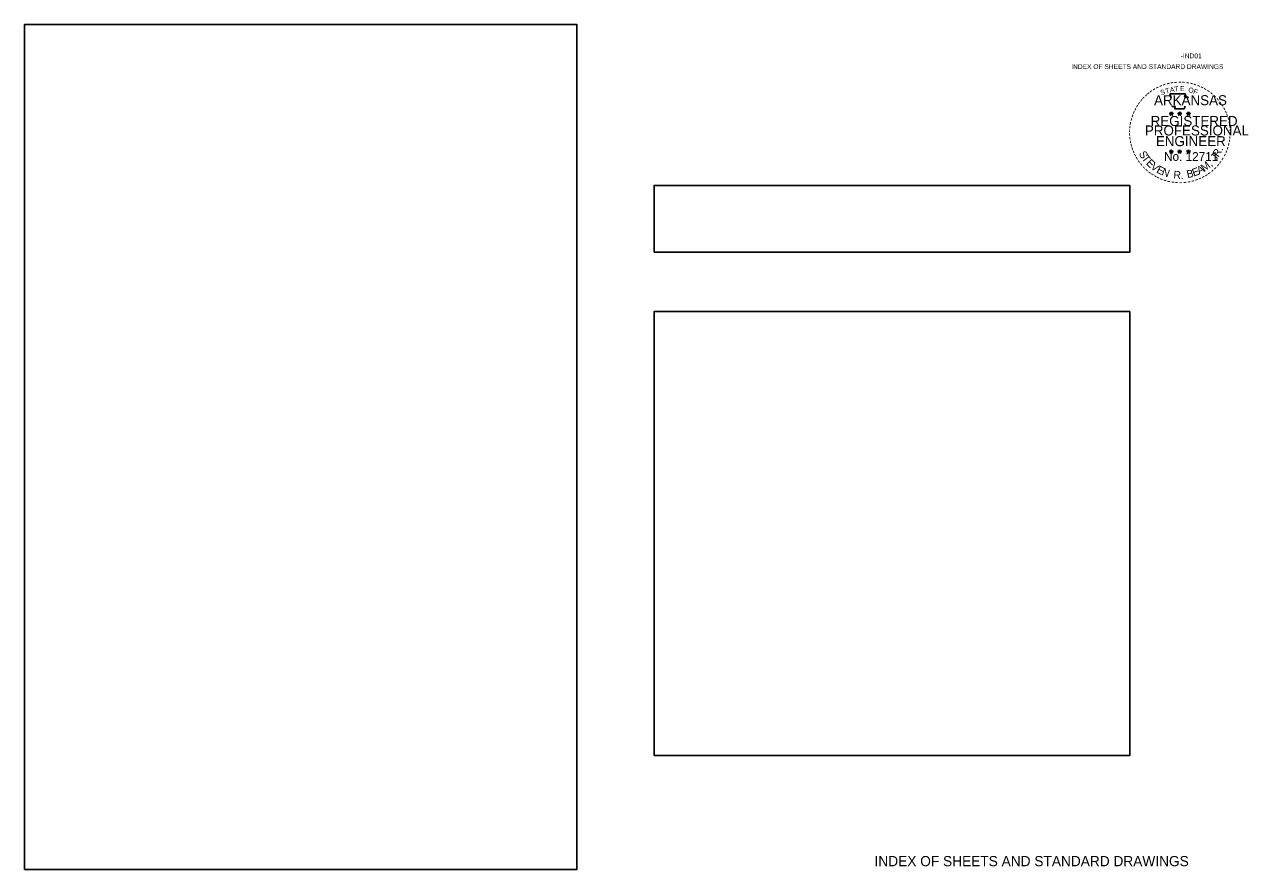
# Model space of a CAD drawing. Extents: x 1224738 to 1228169, y 151309 to 152341.
# Drawn here: x 1226675 to 1228169, y 151309 to 152341 of the extents above; entities that cross this region are included whole.
import ezdxf

# ---------------------------------------------------------------- set-up
doc = ezdxf.new("R2010")
doc.units = 0
doc.layers.add('R_Axis Annot', color=7, linetype='Continuous')
doc.layers.add('R_Border', color=7, linetype='Continuous')

msp = doc.modelspace()

# ---------------------------------------------------------------- linework, layer by layer
at = {"layer": 'R_Axis Annot'}
for p, q in [((1228072.3, 152232.4), (1228074.5, 152231.8)), ((1228072.3, 152232.4), (1228073.9, 152232.2)), ((1228072.3, 152232.4), (1228073.8, 152231.7)), ((1228073.1, 152230), (1228074.5, 152231.8)), ((1228073.1, 152230), (1228073.9, 152231.4)), ((1228073.1, 152230), (1228074.4, 152231.3)), ((1228074.5, 152234), (1228074.2, 152232.5)), ((1228075.8, 152230), (1228074.4, 152231.3)), ((1228074.5, 152231.8), (1228074.5, 152234)), ((1228074.5, 152234), (1228074.8, 152232.5)), ((1228076.6, 152232.4), (1228074.5, 152231.8)), ((1228075.8, 152230), (1228074.5, 152231.8)), ((1228076.6, 152232.4), (1228074.8, 152232.1)), ((1228075.8, 152230), (1228074.9, 152231.7)), ((1228076.6, 152232.4), (1228075.3, 152231.8)), ((1228082.5, 152232.4), (1228084.7, 152231.8)), ((1228082.5, 152232.4), (1228084.1, 152232.2)), ((1228082.5, 152232.4), (1228084, 152231.7)), ((1228083.3, 152230), (1228084.7, 152231.8)), ((1228083.3, 152230), (1228084.1, 152231.4)), ((1228083.3, 152230), (1228084.6, 152231.3)), ((1228084.7, 152234), (1228084.4, 152232.5)), ((1228086, 152230), (1228084.6, 152231.3)), ((1228084.7, 152231.8), (1228084.7, 152234)), ((1228084.7, 152234), (1228085, 152232.5)), ((1228086.8, 152232.4), (1228084.7, 152231.8)), ((1228086, 152230), (1228084.7, 152231.8)), ((1228086.8, 152232.4), (1228085, 152232.1)), ((1228086, 152230), (1228085.1, 152231.7)), ((1228086.8, 152232.4), (1228085.5, 152231.8)), ((1228093.3, 152232.4), (1228095.4, 152231.7)), ((1228093.3, 152232.4), (1228094.8, 152232.1)), ((1228093.3, 152232.4), (1228094.7, 152231.6)), ((1228094.1, 152229.9), (1228095.4, 152231.7)), ((1228094.1, 152229.9), (1228094.9, 152231.4)), ((1228094.1, 152229.9), (1228095.4, 152231.2)), ((1228095.4, 152233.9), (1228095.2, 152232.4)), ((1228095.4, 152231.7), (1228095.4, 152233.9)), ((1228095.4, 152233.9), (1228095.7, 152232.4)), ((1228097.5, 152232.4), (1228095.4, 152231.7)), ((1228096.7, 152229.9), (1228095.4, 152231.7)), ((1228096.7, 152229.9), (1228095.4, 152231.2)), ((1228097.5, 152232.4), (1228095.8, 152232.1)), ((1228096.7, 152229.9), (1228095.9, 152231.7)), ((1228097.5, 152232.4), (1228096.3, 152231.8)), ((1228072.3, 152186.2), (1228074.4, 152185.5)), ((1228072.3, 152186.2), (1228073.8, 152185.9)), ((1228072.3, 152186.2), (1228073.8, 152185.5)), ((1228073.1, 152183.7), (1228074.4, 152185.5)), ((1228073.1, 152183.7), (1228073.9, 152185.2)), ((1228073.1, 152183.7), (1228074.4, 152185.1)), ((1228074.4, 152187.8), (1228074.2, 152186.2)), ((1228074.4, 152185.5), (1228074.4, 152187.8)), ((1228074.4, 152187.8), (1228074.7, 152186.2)), ((1228076.6, 152186.2), (1228074.4, 152185.5)), ((1228075.7, 152183.7), (1228074.4, 152185.5)), ((1228075.7, 152183.7), (1228074.4, 152185)), ((1228076.6, 152186.2), (1228074.8, 152185.9)), ((1228075.7, 152183.7), (1228074.9, 152185.5)), ((1228076.6, 152186.2), (1228075.3, 152185.6)), ((1228082.5, 152186.2), (1228084.6, 152185.5)), ((1228082.5, 152186.2), (1228084, 152185.9)), ((1228082.5, 152186.2), (1228083.9, 152185.5)), ((1228083.3, 152183.7), (1228084.6, 152185.5)), ((1228083.3, 152183.7), (1228084.1, 152185.2)), ((1228083.3, 152183.7), (1228084.6, 152185.1)), ((1228084.6, 152187.8), (1228084.4, 152186.2)), ((1228084.6, 152185.5), (1228084.6, 152187.8)), ((1228084.6, 152187.8), (1228084.9, 152186.2)), ((1228086.7, 152186.2), (1228084.6, 152185.5)), ((1228085.9, 152183.7), (1228084.6, 152185.5)), ((1228085.9, 152183.7), (1228084.6, 152185)), ((1228086.7, 152186.2), (1228085, 152185.9)), ((1228085.9, 152183.7), (1228085.1, 152185.5)), ((1228086.7, 152186.2), (1228085.5, 152185.6)), ((1228093.3, 152186.2), (1228095.4, 152185.5)), ((1228093.3, 152186.2), (1228094.8, 152185.9)), ((1228093.3, 152186.2), (1228094.7, 152185.4)), ((1228094.1, 152183.7), (1228095.4, 152185.5)), ((1228094.1, 152183.7), (1228094.9, 152185.2)), ((1228094.1, 152183.7), (1228095.4, 152185)), ((1228095.4, 152187.7), (1228095.2, 152186.2)), ((1228095.4, 152185.5), (1228095.4, 152187.7)), ((1228095.4, 152187.7), (1228095.7, 152186.2)), ((1228097.5, 152186.2), (1228095.4, 152185.5)), ((1228096.7, 152183.7), (1228095.4, 152185.5)), ((1228096.7, 152183.7), (1228095.4, 152185)), ((1228097.5, 152186.2), (1228095.8, 152185.9)), ((1228096.7, 152183.7), (1228095.9, 152185.4)), ((1228097.5, 152186.2), (1228096.3, 152185.5))]:
    msp.add_line(p, q, dxfattribs=at)
for points in [[(1228072.6, 152256.1), (1228074.2, 152251.1)], [(1228094, 152250.5), (1228094.9, 152252.2), (1228090.7, 152252.1), (1228091.6, 152256.1), (1228072.6, 152256.1)], [(1228075.6, 152241.3), (1228075.6, 152240.8), (1228079, 152240.7), (1228078.7, 152237.8), (1228090.1, 152237.8), (1228091.3, 152241.1)], [(1228074.5, 152234), (1228075.8, 152230), (1228072.3, 152232.4), (1228076.6, 152232.4), (1228073.1, 152230), (1228074.5, 152234)], [(1228084.7, 152234), (1228086, 152230), (1228082.5, 152232.4), (1228086.8, 152232.4), (1228083.3, 152230), (1228084.7, 152234)], [(1228095.4, 152233.9), (1228096.7, 152229.9), (1228093.3, 152232.4), (1228097.5, 152232.4), (1228094.1, 152229.9), (1228095.4, 152233.9)], [(1228074.4, 152187.8), (1228075.7, 152183.7), (1228072.3, 152186.2), (1228076.6, 152186.2), (1228073.1, 152183.7), (1228074.4, 152187.8)], [(1228084.6, 152187.8), (1228085.9, 152183.7), (1228082.5, 152186.2), (1228086.7, 152186.2), (1228083.3, 152183.7), (1228084.6, 152187.8)], [(1228095.4, 152187.7), (1228096.7, 152183.7), (1228093.3, 152186.2), (1228097.5, 152186.2), (1228094.1, 152183.7), (1228095.4, 152187.7)]]:
    msp.add_lwpolyline(points, dxfattribs=at)
for centre, radius in [((1228074.5, 152231.8), 1.05), ((1228074.5, 152231.8), 0.882), ((1228074.5, 152231.8), 0.707), ((1228074.5, 152231.8), 0.605), ((1228074.5, 152231.8), 0.456), ((1228074.5, 152231.8), 0.302), ((1228074.5, 152231.8), 0.181), ((1228084.6, 152231.8), 1.05), ((1228084.6, 152231.8), 0.882), ((1228084.6, 152231.8), 0.707), ((1228084.6, 152231.8), 0.605), ((1228084.6, 152231.8), 0.456), ((1228084.6, 152231.8), 0.302), ((1228084.6, 152231.8), 0.181), ((1228095.4, 152231.7), 1.05), ((1228095.4, 152231.7), 0.882), ((1228095.4, 152231.7), 0.707), ((1228095.4, 152231.7), 0.605), ((1228095.4, 152231.7), 0.456), ((1228095.4, 152231.7), 0.302), ((1228095.4, 152231.7), 0.181), ((1228074.4, 152185.5), 1.05), ((1228074.4, 152185.5), 0.882), ((1228074.4, 152185.5), 0.707), ((1228074.4, 152185.5), 0.605), ((1228074.4, 152185.5), 0.456), ((1228074.4, 152185.5), 0.302), ((1228074.4, 152185.5), 0.181), ((1228084.6, 152185.5), 1.05), ((1228084.6, 152185.5), 0.882), ((1228084.6, 152185.5), 0.707), ((1228084.6, 152185.5), 0.605), ((1228084.6, 152185.5), 0.456), ((1228084.6, 152185.5), 0.302), ((1228084.6, 152185.5), 0.181), ((1228095.4, 152185.5), 1.05), ((1228095.4, 152185.5), 0.882), ((1228095.4, 152185.5), 0.707), ((1228095.4, 152185.5), 0.605), ((1228095.4, 152185.5), 0.456), ((1228095.4, 152185.5), 0.302), ((1228095.4, 152185.5), 0.181)]:
    msp.add_circle(centre, radius, dxfattribs=at)
at = {"layer": 'R_Border'}
for points in [[(1226674.6, 151308.8), (1227348.6, 151308.8), (1227348.6, 152340.8), (1226674.6, 152340.8)], [(1227443.1, 152062.6), (1228023.7, 152062.6), (1228023.7, 152144.2), (1227443.1, 152144.2)], [(1227443.1, 151447.9), (1228023.7, 151447.9), (1228023.7, 151990.2), (1227443.1, 151990.2)]]:
    msp.add_lwpolyline(points, close=True, dxfattribs=at)

# ---------------------------------------------------------------- texts
at = {"layer": 'R_Axis Annot'}
for s, height, p in [('-IND01', 5.86, (1228085.9, 152299.5)), ('INDEX OF SHEETS AND STANDARD DRAWINGS', 5.862, (1227952.3, 152286.4)), ('ARKANSAS', 12.21, (1228053.4, 152242.2)), ('REGISTERED', 12.21, (1228049.2, 152216.8)), ('PROFESSIONAL', 12.208, (1228042.2, 152205.2)), ('ENGINEER', 12.21, (1228055.6, 152192.2)), ('No. 12711', 10.72, (1228065.6, 152174.2))]:
    msp.add_text(s, height=height, dxfattribs=at).set_placement(p)
for s, height, rotation, p in [('-', 9.77, 24.3072, (1228061.1, 152261.4)), ('-', 9.77, 19.1761, (1228064.9, 152263)), ('-', 9.77, 13.6302, (1228069.5, 152264.5)), ('-', 9.77, 10.2193, (1228073.7, 152265.5)), ('-', 9.77, 5.8968, (1228078.1, 152266.1)), ('-', 9.77, 0.1862, (1228082.8, 152266.6)), ('E', 6.1, 0.8323, (1228085.1, 152259.4)), ('-', 9.77, 357.743, (1228087.2, 152266.5)), ('-', 9.77, 352.1617, (1228091.8, 152266.1)), ('-', 9.77, 347.2049, (1228096.2, 152265.5)), ('-', 9.77, 342.3362, (1228100, 152264.5)), ('-', 9.77, 337.8551, (1228104.5, 152263.1)), ('-', 9.77, 48.4231, (1228041.7, 152247)), ('-', 9.77, 42.9622, (1228044.5, 152249.9)), ('-', 9.77, 38.9507, (1228047.1, 152252.4)), ('-', 9.77, 36.2317, (1228050, 152254.8)), ('-', 9.77, 34.0636, (1228053.6, 152257.2)), ('-', 9.77, 28.7918, (1228057.2, 152259.4)), ('S', 6.1, 21.594, (1228062.5, 152254.2)), ('T', 6.1, 16.4036, (1228068.1, 152256.2)), ('A', 6.1, 11.2132, (1228073.2, 152257.7)), ('T', 6.1, 6.0228, (1228078.3, 152258.7)), ('O', 6.1, 350.4515, (1228094.9, 152258.1)), ('F', 6.1, 340.0707, (1228100.7, 152256.7)), ('-', 9.77, 334.1211, (1228108.4, 152261.5)), ('-', 9.77, 329.6409, (1228111.9, 152259.8)), ('-', 9.77, 325.8627, (1228115.8, 152257.6)), ('-', 9.77, 320.5297, (1228119.6, 152255)), ('-', 9.77, 315.5786, (1228123.2, 152252)), ('-', 9.77, 309.8797, (1228126.7, 152248.6)), ('-', 9.77, 62.8713, (1228032.9, 152233.6)), ('-', 9.77, 58.0706, (1228034.8, 152237.3)), ('-', 9.77, 54.2325, (1228036.8, 152240.6)), ('-', 9.77, 50.6142, (1228039.3, 152244)), ('-', 9.77, 306.6522, (1228129.9, 152244.9)), ('-', 8.55, 303.6753, (1228132.9, 152241.5)), ('-', 9.77, 299.6684, (1228134.8, 152237.8)), ('-', 9.77, 81.2013, (1228027.9, 152217.3)), ('-', 9.77, 75.461, (1228028.8, 152221.7)), ('-', 9.77, 72.3945, (1228030, 152226)), ('-', 9.77, 67.7743, (1228031.3, 152229.9)), ('-', 9.77, 294.6628, (1228136.8, 152234)), ('-', 9.77, 290.5728, (1228138.3, 152230.5)), ('-', 9.77, 285.1233, (1228139.8, 152227)), ('-', 9.77, 280.5493, (1228141, 152222.5)), ('-', 9.77, 89.0622, (1228027.3, 152208.8)), ('-', 9.77, 94.1959, (1228027.5, 152204.4)), ('-', 9.77, 85.1863, (1228027.5, 152213.1)), ('-', 9.77, 276.5962, (1228142, 152217.8)), ('-', 9.77, 274.3301, (1228142.4, 152213.4)), ('-', 9.77, 269.9407, (1228142.6, 152209.5)), ('-', 9.77, 98.9479, (1228028, 152200.3)), ('-', 9.77, 101.7149, (1228028.8, 152195.8)), ('-', 9.77, 105.4578, (1228029.8, 152192.2)), ('-', 9.77, 109.0874, (1228031.1, 152188.4)), ('-', 9.77, 252.8681, (1228140.2, 152192.9)), ('-', 9.77, 255.7626, (1228141.3, 152197.3)), ('-', 9.77, 260.9953, (1228142, 152201.4)), ('-', 9.77, 263.5172, (1228142.4, 152205.4)), ('-', 9.77, 114.0643, (1228032.7, 152184.7)), ('-', 9.77, 115.7289, (1228034.5, 152180.9)), ('-', 9.77, 120.4471, (1228036.7, 152177.4)), ('S', 9.4, 299.1736, (1228034.4, 152183.1)), ('T', 9.4, 307.2838, (1228037.9, 152177.1)), ('E', 9.4, 315.394, (1228043.1, 152170.6)), ('J', 9.4, 52.7162, (1228128.6, 152173.2)), ('R.', 9.4, 60.8264, (1228132.2, 152178)), ('-', 9.77, 239.0712, (1228134.9, 152180.4)), ('-', 9.77, 244.6197, (1228137.3, 152185)), ('-', 9.77, 247.8887, (1228138.9, 152188.8)), ('-', 9.77, 125.8934, (1228039.2, 152173.9)), ('-', 9.77, 130.7181, (1228042, 152170.6)), ('-', 9.77, 134.2238, (1228045.1, 152167.2)), ('-', 9.77, 138.9338, (1228048.3, 152164.4)), ('-', 9.77, 144.6463, (1228051.7, 152161.9)), ('V', 9.4, 323.5042, (1228048.4, 152165.4)), ('E', 9.4, 331.6144, (1228055.5, 152160.5)), ('N', 9.4, 339.7245, (1228061.9, 152157.1)), ('R.', 9.4, 355.9449, (1228076.8, 152152.8)), ('B', 9.4, 12.1653, (1228094.2, 152153.1)), ('E', 9.4, 20.2755, (1228101.8, 152155)), ('A', 9.4, 28.3856, (1228108.5, 152157.5)), ('M,', 9.4, 36.4958, (1228114.6, 152160.7)), ('-', 9.77, 221.0851, (1228123.7, 152166.4)), ('-', 9.77, 225.7653, (1228126.9, 152169.5)), ('-', 9.77, 231.2538, (1228129.8, 152172.9)), ('-', 9.77, 233.8452, (1228132.4, 152176.4)), ('-', 9.77, 148.0898, (1228055.2, 152159.7)), ('-', 9.77, 151.5704, (1228058.7, 152157.7)), ('-', 9.77, 154.6002, (1228061.9, 152156.2)), ('-', 9.77, 158.5612, (1228065.7, 152154.6)), ('-', 9.77, 162.7983, (1228069.9, 152153.3)), ('-', 9.77, 167.5555, (1228074.2, 152152.3)), ('-', 9.77, 173.1155, (1228079, 152151.7)), ('-', 9.77, 176.5183, (1228083.5, 152151.3)), ('-', 9.77, 181.5918, (1228088.1, 152151.4)), ('-', 9.77, 185.8167, (1228093, 152151.9)), ('-', 9.77, 191.2858, (1228097.5, 152152.7)), ('-', 9.77, 195.4743, (1228101.9, 152153.9)), ('-', 9.77, 200.7184, (1228106.1, 152155.4)), ('-', 9.77, 204.2516, (1228109.9, 152157.1)), ('-', 9.77, 207.3568, (1228113.7, 152159)), ('-', 9.77, 212.2491, (1228117.1, 152161.1)), ('-', 9.77, 215.7363, (1228120.3, 152163.5))]:
    msp.add_text(s, height=height, rotation=rotation, dxfattribs=at).set_placement(p)
at = {"layer": 'R_Border'}
msp.add_text('INDEX OF SHEETS AND STANDARD DRAWINGS', height=12.5, dxfattribs=at).set_placement((1227712.2, 151312.8))

doc.saveas('drawing.dxf')
